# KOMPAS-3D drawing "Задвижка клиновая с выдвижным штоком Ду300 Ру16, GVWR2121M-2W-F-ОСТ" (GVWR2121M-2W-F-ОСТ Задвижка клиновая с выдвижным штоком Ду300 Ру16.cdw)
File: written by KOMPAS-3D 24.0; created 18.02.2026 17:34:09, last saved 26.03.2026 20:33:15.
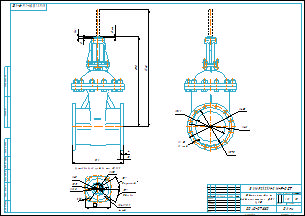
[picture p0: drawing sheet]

Document properties: Автор: R2D2; Форматы листов документа: A2; Полное имя файла: GVWR2121M-2W-F-ОСТ Задвижка клиновая с видвижным штоком Ду300 Ру16.cdw; Масса: 210; Наименование: Задвижка клиновая с выдвижным штоком Ду300 Ру16; Количество листов документа: 1; Примечание: D040-07880

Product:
- Part/product: Задвижка клиновая с выдвижным штоком Ду300 Ру16  | designation GVWR2121M-2W-F-ОСТ
    Масса: 210
    Раздел спецификации: Прочие изделия
    Форматы листов документа: A2
    Примечание: D040-07880

Views: Проекционный вид 2
Referenced files in E:\Работа\Зайцев\Для компаса\: чертеж DN.ru А3.cdt
Referenced files in E:\Работа\Зайцев\GVWR2121M-2W-F-ОСТ Задвижка клиновая с видвижным штоком Ду50-300 Ру16\DN300\: GVWR2121M-2W-F-ОСТ Задвижка клиновая с выдвижным штоком Ду300 Ру16.m3d
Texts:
  Присоединение привода тип АК (Б)
  чертеж DN.ru А3.cdt
  Задвижка клиновая с
  выдвижным штоком Ду300
  Ру16
  GVWR2121M-2W-F-ОСТ
  Задвижка клиновая с выдвижным штоком Ду300 Ру16
  GVWR2121M-2W-F-ОСТ Задвижка клиновая с выдвижным штоком Ду300 Ру16
Dimensions and other numbers on the sheet: 108; 45; 59; 135; 13; 14 (М12); 4 отв.; 122; 5 впадин; 5 кулачков; 1:5; 0; 1; 2; 210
